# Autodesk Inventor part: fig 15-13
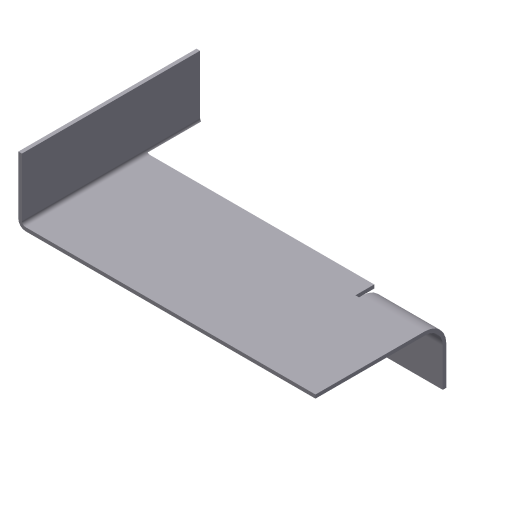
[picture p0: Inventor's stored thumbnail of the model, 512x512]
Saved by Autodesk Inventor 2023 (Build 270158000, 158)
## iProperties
Created: 2002-04
Part Number: fig 15-13
Material: Aluminum-6061
Document SubType Name: Sheet Metal
Density: 1 g/cm^3
Sheet Metal Rule: Default
Appearance: Aluminum - Flat-1
Control State: 0
Master: False
Checked Out: False
Shininess: 77.0
Angle Display Precision: 2
Document Length Units: 11269
Document Angle Units: 11279
Document Time Units: 11290
Document Mass Units: 11283
Document Length Units Precision: 3
Document Angle Units Precision: 2
Density: 0.0
Volumn: 0.0
Area: 0.0
PropertySet Name: Model Information
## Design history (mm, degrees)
node "Face1"
  sketch "Sketch1"
    geometry: L1 (-49.559, 19.574)-(-49.559, -30.426); L2 (-49.559, -30.426)-(50.441, -30.426); L3 (50.441, -30.426)-(50.441, 19.574); L4 (50.441, 19.574)-(32.941, 19.574); L5 (32.941, 19.574)-(32.941, 4.574); L6 (32.941, 4.574)-(-32.059, 4.574); L7 (-32.059, 4.574)-(-32.059, 19.574); L8 (-32.059, 19.574)-(-49.559, 19.574)
    constraints: 16 end point, 6 parallel, 2 equal length, 1 perpendicular, 1 vertical
    dimensions: "d0" = 100 distance of L1.end L2.end; "d1" = 65 distance of L5.end L6.end; "d2" = 15 distance of L6.end L7.end; "d3" = 50 distance of L1.start L1.end
sketch "Sketch2"
  geometry: L1 (100, 0)-(0, 0) reference; L2 (17.5, 50)-(17.5, 35) reference; L3 (82.5, 50)-(82.5, 0)
  constraints: 2 end point, 1 parallel, 1 point on line
sketch "Sketch3"
  geometry: L1 (81.369, -50)-(0, -50) reference; L2 (17.5, 0)-(17.5, -50)
  constraints: 2 end point, 1 perpendicular, 1 point on line
feature "Fold2" sketch "Sketch3" dims "d8" = 1 (= BendRadius), "d9" = 90 deg, "d10" = 1 (= BendRadius), "d14" = 1 (= BendReliefWidth), "d15" = 0.5 (= BendReliefDepth), "d16" = 2 (= MinimumRemnant), "d20" = 1 (= Thickness), "SeamGap" = 0.01
sketch "Sketch4"
  geometry: L1 (17.5, 0)-(17.5, -50) reference; L2 (-63.869, -15)-(0, -15) reference; L3 (0, -15)-(17.5, -15)
  constraints: 2 end point, 1 collinear, 1 point on line
feature "Fold3" sketch "Sketch4" dims "d11" = 1 (= BendRadius), "d12" = 90 deg, "d13" = 5, "d17" = 1 (= BendReliefWidth), "d18" = 1, "d19" = 2 (= MinimumRemnant), "d20" = 1 (= Thickness), "SeamGap" = 0.01
body "Solid1"
face "Plate1" dims "d20" = 1 (= Thickness)
other parameters: "Thickness" = 1, "BendRadius" = 1 (= Thickness), "BendReliefWidth" = 1 (= Thickness), "BendReliefDepth" = 0.5 (= 0.5 x Thickness), "CornerReliefSize" = 4 (= 4 x Thickness), "MinimumRemnant" = 2 (= 2 x Thickness), "TransitionRadius" = 1 (= BendRadius), "d4" = 1 (= BendRadius), "JacobiRadiusSize" = 1 (= Thickness), "GapSize" = 1 (= Thickness)
